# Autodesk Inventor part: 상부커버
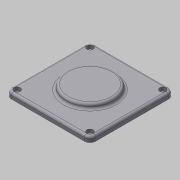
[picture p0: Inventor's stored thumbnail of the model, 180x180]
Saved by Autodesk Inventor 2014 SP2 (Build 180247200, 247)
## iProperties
Created: 2018-09
Part Number: 상부커버
Document SubType Name: Modeling
Density: 2.71 g/cm^3
Material: 알루미늄 6061
Mass: 115.614 g
Surface Area: 104.313 cm^2
Volume: 42.662 cm^3
Appearance: 알루미늄 - 평지
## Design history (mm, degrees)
sketch "스케치5"
  geometry: L1 (-52.5, -52.5)-(52.5, -52.5); L2 (52.5, -52.5)-(52.5, 52.5); L3 (52.5, 52.5)-(-52.5, 52.5); L4 (-52.5, 52.5)-(-52.5, -52.5); L5 (-52.5, -52.5)-(52.5, 52.5); L6 (52.5, -52.5)-(-52.5, 52.5); 1 further point
  constraints: 12 end point, 2 midpoint, 2 parallel, 1 horizontal, 1 perpendicular
  dimensions: "d35" = 105 distance of L3.end L2.end; "d36" = 105 distance of L2.end L1.end
extrude "돌출4" new body sketch "스케치5" distance "d37" = 7; taper "d38" = 0 deg
fillet "모깎기4" dims "d39" = 7
sketch "스케치2"
  geometry: C1 r 30 at (0, 0); 2 further points
  constraints: 2 coincident, 1 centre point
  dimensions: "d4" = 60 diameter of C1
extrude "돌출3" join sketch "스케치2" distance "d5" = 6; taper "d6" = 0 deg
fillet "모깎기1" dims "d7" = 3
sketch "스케치4"
  geometry: L1 (52.5, -45.5)-(52.5, 45.5) reference; L2 (-45.5, -52.5)-(45.5, -52.5) reference; L3 (-52.5, 45.5)-(-52.5, -45.5) reference; L4 (45.5, 52.5)-(-45.5, 52.5) reference; A1 r 7 centre (45.5, 45.5) between (52.5, 45.5) and (45.5, 52.5) reference; A2 r 7 centre (45.5, -45.5) between (45.5, -52.5) and (52.5, -45.5) reference; A3 r 7 centre (-45.5, -45.5) between (-52.5, -45.5) and (-45.5, -52.5) reference; A4 r 7 centre (-45.5, 45.5) between (-45.5, 52.5) and (-52.5, 45.5) reference; 4 further points
  constraints: 4 coincident
hole "구멍3" sketch "스케치4" at (-45.5, 45.5), (-45.5, -45.5), (45.5, -45.5), (45.5, 45.5) diameter "d43" = 4.5; stored, may be unused: countersink angle "d47" = 90 deg, drill point angle "d49" = 118 deg; dims "d44" = 6, "d45" = 8, "d46" = 4.4, "d48" = 8
fillet "모깎기3" dims "d19" = 3
node "솔리드1"
node "솔리드2"
node "투영된 루프2"
